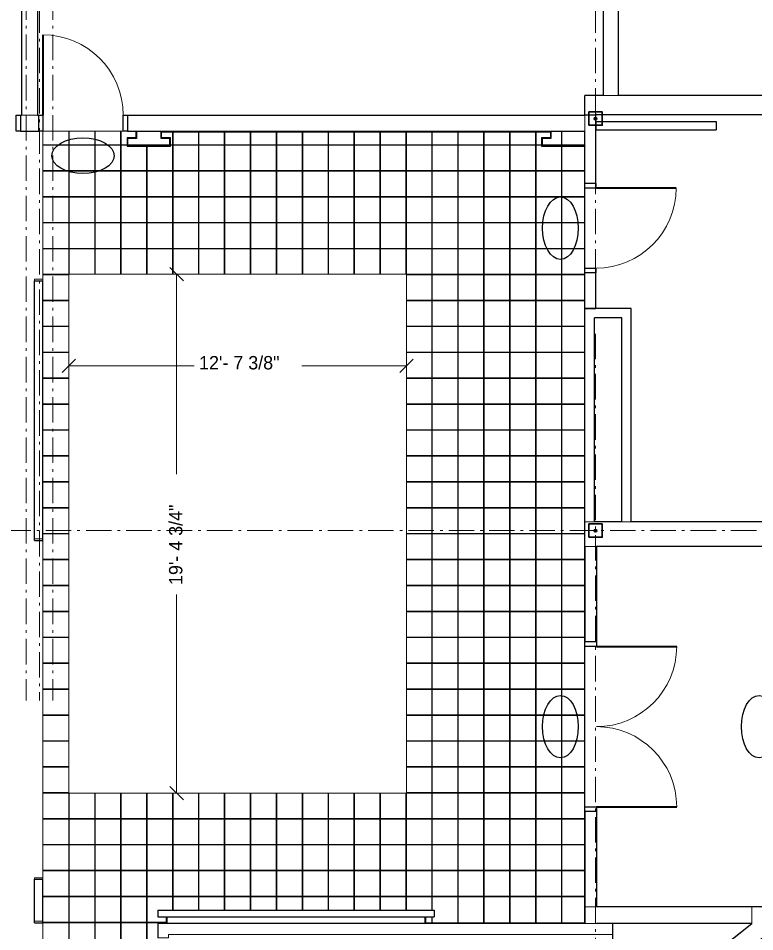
# Model space of a CAD drawing. Extents: x 10076 to 10305, y 10052 to 10157.
# Drawn here: x 10183.75 to 10211.27, y 10095.45 to 10129.6 of the extents above; entities that cross this region are included whole.
import ezdxf

# ---------------------------------------------------------------- set-up
doc = ezdxf.new("R2010")
doc.units = 0
doc.header["$LTSCALE"] = 0.19
doc.header["$PDMODE"] = 32
doc.header["$PDSIZE"] = 0.095
doc.linetypes.add('DOT_DASHED', pattern=[7.7, 5, -1.2, 0.3, -1.2])
for name, color, linetype, lineweight in [('1', 7, 'Continuous', 13), ('10', 7, 'DOT_DASHED', 13), ('12', 7, 'Continuous', 35), ('18', 7, 'Continuous', 13), ('23', 7, 'Continuous', 25), ('25', 7, 'Continuous', 13), ('26', 7, 'Continuous', 25), ('42', 7, 'Continuous', 25)]:
    doc.layers.add(name, color=color, linetype=linetype, lineweight=lineweight)

msp = doc.modelspace()

# ---------------------------------------------------------------- linework, layer by layer
at = {"layer": '1'}
for points in [[(10183.8669, 10125.9796), (10183.8669, 10140.2504), (10184.4711, 10140.2504), (10184.4711, 10125.9796)], [(10205.6117, 10140.2504), (10205.6117, 10126.7087), (10206.1742, 10126.7087), (10206.1742, 10140.2504)], [(10204.9242, 10126.7087), (10204.9242, 10125.99), (10223.8513, 10125.99), (10223.8513, 10126.7087)], [(10183.8356, 10125.9796), (10183.8356, 10125.3754), (10184.5023, 10125.3754), (10184.5023, 10125.9796)], [(10187.8356, 10125.9796), (10187.8356, 10125.3754), (10204.9242, 10125.3754), (10204.9242, 10125.9796)], [(10205.3304, 10123.4171), (10205.3304, 10125.9796), (10204.9242, 10125.9796), (10204.9242, 10123.4171)], [(10205.3304, 10125.99), (10205.3304, 10125.7386), (10205.5705, 10125.7386), (10205.5705, 10125.99)], [(10209.8304, 10125.4275), (10209.8304, 10125.74), (10205.3304, 10125.74), (10205.3304, 10125.4275)], [(10188.1481, 10125.3754), (10188.1481, 10125.1254), (10187.8148, 10125.1254), (10187.8148, 10124.8129), (10189.4398, 10124.8129), (10189.4398, 10125.1254), (10189.1065, 10125.1254), (10189.1065, 10125.3754)], [(10203.6325, 10125.3754), (10203.6325, 10125.1254), (10203.2992, 10125.1254), (10203.2992, 10124.8129), (10204.9242, 10124.8129), (10204.9242, 10125.3754)], [(10184.3565, 10119.8389), (10184.3565, 10110.1306), (10184.669, 10110.1306), (10184.669, 10119.8389)], [(10204.9242, 10120.0837), (10204.9242, 10118.7504), (10205.3304, 10118.7504), (10205.3304, 10120.0837)], [(10204.9242, 10118.7504), (10204.9242, 10110.766), (10206.6534, 10110.766), (10206.6534, 10118.7504)], [(10204.9242, 10109.8493), (10204.9242, 10110.766), (10224.8926, 10110.766), (10224.8926, 10109.8493)], [(10205.3513, 10109.8493), (10205.3513, 10106.2817), (10204.9242, 10106.2817), (10204.9242, 10109.8493)], [(10204.9242, 10099.9484), (10204.9242, 10096.3806), (10205.3513, 10096.3806), (10205.3513, 10099.9484)], [(10184.3565, 10097.4639), (10184.3565, 10095.8389), (10184.669, 10095.8389), (10184.669, 10097.4639)], [(10211.1603, 10095.7556), (10211.1603, 10096.3806), (10204.9242, 10096.3806), (10204.9242, 10095.7556)], [(10211.1603, 10096.3806), (10213.0179, 10096.3806), (10206.1076, 10090.8876), (10205.6117, 10090.8858), (10205.6117, 10091.6266), (10205.9659, 10091.6266), (10211.1603, 10095.7556)], [(10189.3669, 10095.3493), (10189.3669, 10095.2191), (10188.9606, 10095.2191), (10188.9606, 10095.7556), (10205.9659, 10095.7556), (10205.9659, 10095.3493)]]:
    msp.add_lwpolyline(points, close=True, dxfattribs=at)
at = {"layer": '10'}
for p, q in [((10184.544, 10154.0964), (10184.544, 10104.0964)), ((10205.32, 10154.0964), (10205.32, 10118.7504)), ((10184.044, 10151.5744), (10184.044, 10104.0964)), ((10185.044, 10151.5744), (10185.044, 10104.0964)), ((10205.32, 10117.8041), (10205.32, 10071.3549)), ((10227.8946, 10110.4431), (10179.5805, 10110.4431))]:
    msp.add_line(p, q, dxfattribs=at)
at = {"layer": '12'}
for points in [[(10205.07, 10125.5941), (10205.07, 10126.0941), (10205.57, 10126.0941), (10205.57, 10125.5941)], [(10205.07, 10110.1931), (10205.07, 10110.6931), (10205.57, 10110.6931), (10205.57, 10110.1931)]]:
    msp.add_lwpolyline(points, close=True, dxfattribs=at)
for p in [(10205.32, 10125.8441), (10205.32, 10110.4431)]:
    msp.add_point(p, dxfattribs=at)
at = {"layer": '18'}
for p, q in [((10184.669, 10078.5525), (10184.669, 10125.3754)), ((10184.669, 10125.3754), (10187.669, 10125.3754)), ((10185.6377, 10075.4639), (10185.6377, 10125.3754)), ((10185.6586, 10120.0264), (10185.6586, 10125.3754)), ((10186.6065, 10120.0264), (10186.6065, 10125.3754)), ((10186.6273, 10120.0264), (10186.6273, 10125.3754)), ((10187.5752, 10120.0264), (10187.5752, 10125.3754)), ((10187.5961, 10120.0264), (10187.5961, 10125.3754)), ((10203.6325, 10125.3441), (10189.1065, 10125.3441)), ((10189.5127, 10120.0264), (10189.5127, 10125.3754)), ((10189.5336, 10120.0264), (10189.5336, 10125.3754)), ((10190.4815, 10120.0264), (10190.4815, 10125.3754)), ((10190.5023, 10120.0264), (10190.5023, 10125.3754)), ((10191.4502, 10120.0264), (10191.4502, 10125.3754)), ((10191.4711, 10120.0264), (10191.4711, 10125.3754)), ((10192.419, 10120.0264), (10192.419, 10125.3754)), ((10192.4398, 10120.0264), (10192.4398, 10125.3754)), ((10193.3877, 10120.0264), (10193.3877, 10125.3754)), ((10193.4086, 10120.0264), (10193.4086, 10125.3754)), ((10194.3565, 10120.0264), (10194.3565, 10125.3754)), ((10194.3773, 10120.0264), (10194.3773, 10125.3754)), ((10195.3252, 10120.0264), (10195.3252, 10125.3754)), ((10195.3461, 10120.0264), (10195.3461, 10125.3754)), ((10196.294, 10120.0264), (10196.294, 10125.3754)), ((10196.3148, 10120.0264), (10196.3148, 10125.3754)), ((10197.2627, 10120.0264), (10197.2627, 10125.3754)), ((10197.2836, 10120.0264), (10197.2836, 10125.3754)), ((10198.2315, 10120.0264), (10198.2315, 10125.3754)), ((10198.2523, 10096.2556), (10198.2523, 10125.3754)), ((10199.2002, 10096.2523), (10199.2002, 10125.3754)), ((10199.2211, 10096.2523), (10199.2211, 10125.3754)), ((10200.169, 10095.7764), (10200.169, 10125.3754)), ((10200.1898, 10095.7764), (10200.1898, 10125.3754)), ((10201.1377, 10095.7764), (10201.1377, 10125.3754)), ((10201.1586, 10095.7764), (10201.1586, 10125.3754)), ((10202.1065, 10095.7764), (10202.1065, 10125.3754)), ((10202.1273, 10095.7764), (10202.1273, 10125.3754)), ((10203.0752, 10095.7764), (10203.0752, 10125.3754)), ((10203.0961, 10095.7764), (10203.0961, 10125.3754)), ((10204.044, 10095.7764), (10204.044, 10125.3754)), ((10204.0648, 10095.7764), (10204.0648, 10125.3754)), ((10184.669, 10124.8702), (10204.9034, 10124.8702)), ((10184.669, 10124.8493), (10204.9034, 10124.8493)), ((10188.544, 10120.0264), (10188.544, 10124.8129)), ((10188.5648, 10120.0264), (10188.5648, 10124.8129)), ((10204.9034, 10095.7556), (10204.9034, 10124.8129)), ((10184.669, 10123.9014), (10204.9034, 10123.9014)), ((10184.669, 10123.8806), (10204.9034, 10123.8806)), ((10204.9242, 10123.2504), (10204.9242, 10120.2504)), ((10184.669, 10122.9327), (10204.9034, 10122.9327)), ((10184.669, 10122.9118), (10204.9034, 10122.9118)), ((10184.669, 10121.9639), (10204.9034, 10121.9639)), ((10184.669, 10121.9431), (10204.9034, 10121.9431)), ((10184.669, 10120.9952), (10204.9034, 10120.9952)), ((10184.669, 10120.9743), (10204.9034, 10120.9743)), ((10189.419, 10120.2764), (10189.919, 10119.7764)), ((10184.669, 10120.0264), (10204.9034, 10120.0264)), ((10184.669, 10120.0056), (10185.6377, 10120.0056)), ((10189.669, 10120.0264), (10189.669, 10112.5488)), ((10198.2523, 10120.0056), (10204.9034, 10120.0056)), ((10184.669, 10119.0577), (10185.6377, 10119.0577)), ((10184.669, 10119.0368), (10185.6377, 10119.0368)), ((10198.2523, 10119.0577), (10204.9034, 10119.0577)), ((10198.2523, 10119.0368), (10204.9034, 10119.0368)), ((10184.669, 10118.0889), (10185.6377, 10118.0889)), ((10184.669, 10118.0681), (10185.6377, 10118.0681)), ((10198.2523, 10118.0889), (10204.9034, 10118.0889)), ((10198.2523, 10118.0681), (10204.9034, 10118.0681)), ((10184.669, 10117.1202), (10185.6377, 10117.1202)), ((10184.669, 10117.0993), (10185.6377, 10117.0993)), ((10198.2523, 10117.1202), (10204.9034, 10117.1202)), ((10198.2523, 10117.0993), (10204.9034, 10117.0993)), ((10185.3877, 10116.3493), (10185.8877, 10116.8493)), ((10198.0023, 10116.3493), (10198.5023, 10116.8493)), ((10185.6377, 10116.5993), (10190.3206, 10116.5993)), ((10194.3486, 10116.5993), (10198.2523, 10116.5993)), ((10184.669, 10116.1514), (10185.6377, 10116.1514)), ((10184.669, 10116.1306), (10185.6377, 10116.1306)), ((10198.2523, 10116.1514), (10204.9034, 10116.1514)), ((10198.2523, 10116.1306), (10204.9034, 10116.1306)), ((10184.669, 10115.1827), (10185.6377, 10115.1827)), ((10184.669, 10115.1618), (10185.6377, 10115.1618)), ((10198.2523, 10115.1827), (10204.9034, 10115.1827)), ((10198.2523, 10115.1618), (10204.9034, 10115.1618)), ((10184.669, 10114.2139), (10185.6377, 10114.2139)), ((10184.669, 10114.1931), (10185.6377, 10114.1931)), ((10198.2523, 10114.2139), (10204.9034, 10114.2139)), ((10198.2523, 10114.1931), (10204.9034, 10114.1931)), ((10184.669, 10113.2452), (10185.6377, 10113.2452)), ((10184.669, 10113.2243), (10185.6377, 10113.2243)), ((10198.2523, 10113.2452), (10204.9034, 10113.2452)), ((10198.2523, 10113.2243), (10204.9034, 10113.2243)), ((10184.669, 10112.2764), (10185.6377, 10112.2764)), ((10184.669, 10112.2556), (10185.6377, 10112.2556)), ((10198.2523, 10112.2764), (10204.9034, 10112.2764)), ((10198.2523, 10112.2556), (10204.9034, 10112.2556)), ((10184.669, 10111.3077), (10185.6377, 10111.3077)), ((10184.669, 10111.2868), (10185.6377, 10111.2868)), ((10198.2523, 10111.3077), (10204.9034, 10111.3077)), ((10198.2523, 10111.2868), (10204.9034, 10111.2868)), ((10184.669, 10110.3389), (10185.6377, 10110.3389)), ((10184.669, 10110.3181), (10185.6377, 10110.3181)), ((10198.2523, 10110.3389), (10204.9034, 10110.3389)), ((10198.2523, 10110.3181), (10204.9034, 10110.3181)), ((10184.669, 10109.3702), (10185.6377, 10109.3702)), ((10184.669, 10109.3493), (10185.6377, 10109.3493)), ((10198.2523, 10109.3702), (10204.9034, 10109.3702)), ((10198.2523, 10109.3493), (10204.9034, 10109.3493)), ((10184.669, 10108.4014), (10185.6377, 10108.4014)), ((10184.669, 10108.3806), (10185.6377, 10108.3806)), ((10198.2523, 10108.4014), (10204.9034, 10108.4014)), ((10198.2523, 10108.3806), (10204.9034, 10108.3806)), ((10189.669, 10108.0527), (10189.669, 10100.6306)), ((10184.669, 10107.4327), (10185.6377, 10107.4327)), ((10184.669, 10107.4118), (10185.6377, 10107.4118)), ((10198.2523, 10107.4327), (10204.9034, 10107.4327)), ((10198.2523, 10107.4118), (10204.9034, 10107.4118)), ((10184.669, 10106.4639), (10185.6377, 10106.4639)), ((10184.669, 10106.4431), (10185.6377, 10106.4431)), ((10198.2523, 10106.4639), (10204.9034, 10106.4639)), ((10198.2523, 10106.4431), (10204.9034, 10106.4431)), ((10204.9242, 10100.1151), (10204.9242, 10106.1151)), ((10184.669, 10105.4952), (10185.6377, 10105.4952)), ((10184.669, 10105.4743), (10185.6377, 10105.4743)), ((10198.2523, 10105.4952), (10204.9034, 10105.4952)), ((10198.2523, 10105.4743), (10204.9034, 10105.4743)), ((10184.669, 10104.5264), (10185.6377, 10104.5264)), ((10184.669, 10104.5056), (10185.6377, 10104.5056)), ((10198.2523, 10104.5264), (10204.9034, 10104.5264)), ((10198.2523, 10104.5056), (10204.9034, 10104.5056)), ((10184.669, 10103.5577), (10185.6377, 10103.5577)), ((10184.669, 10103.5368), (10185.6377, 10103.5368)), ((10198.2523, 10103.5577), (10204.9034, 10103.5577)), ((10198.2523, 10103.5368), (10204.9034, 10103.5368)), ((10184.669, 10102.5889), (10185.6377, 10102.5889)), ((10184.669, 10102.5681), (10185.6377, 10102.5681)), ((10198.2523, 10102.5889), (10204.9034, 10102.5889)), ((10198.2523, 10102.5681), (10204.9034, 10102.5681)), ((10184.669, 10101.6202), (10185.6377, 10101.6202)), ((10184.669, 10101.5993), (10185.6377, 10101.5993)), ((10198.2523, 10101.6202), (10204.9034, 10101.6202)), ((10198.2523, 10101.5993), (10204.9034, 10101.5993)), ((10184.669, 10100.6514), (10185.6377, 10100.6514)), ((10189.419, 10100.8806), (10189.919, 10100.3806)), ((10198.2523, 10100.6514), (10204.9034, 10100.6514)), ((10184.669, 10100.6306), (10204.9034, 10100.6306)), ((10185.6586, 10075.4639), (10185.6586, 10100.6304)), ((10186.6065, 10075.4639), (10186.6065, 10100.6306)), ((10186.6273, 10075.4639), (10186.6273, 10100.6306)), ((10187.5752, 10075.4639), (10187.5752, 10100.6306)), ((10187.5961, 10075.4639), (10187.5961, 10100.6306)), ((10188.544, 10075.4639), (10188.544, 10100.6306)), ((10188.5648, 10075.4639), (10188.5648, 10100.6306)), ((10189.5127, 10096.2556), (10189.5127, 10100.6306)), ((10189.5336, 10096.2556), (10189.5336, 10100.6306)), ((10190.4815, 10096.2556), (10190.4815, 10100.6306)), ((10190.5023, 10096.2556), (10190.5023, 10100.6306)), ((10191.4502, 10096.2556), (10191.4502, 10100.6306)), ((10191.4711, 10096.2556), (10191.4711, 10100.6306)), ((10192.419, 10096.2556), (10192.419, 10100.6306)), ((10192.4398, 10096.2556), (10192.4398, 10100.6306)), ((10193.3877, 10096.2556), (10193.3877, 10100.6306)), ((10193.4086, 10096.2556), (10193.4086, 10100.6306)), ((10194.3565, 10096.2556), (10194.3565, 10100.6306)), ((10194.3773, 10096.2556), (10194.3773, 10100.6306)), ((10195.3252, 10096.2556), (10195.3252, 10100.6306)), ((10195.3461, 10096.2556), (10195.3461, 10100.6306)), ((10196.294, 10096.2556), (10196.294, 10100.6306)), ((10196.3148, 10096.2556), (10196.3148, 10100.6306)), ((10197.2627, 10096.2556), (10197.2627, 10100.6306)), ((10197.2836, 10096.2556), (10197.2836, 10100.6306)), ((10198.2315, 10096.2556), (10198.2315, 10100.6306)), ((10184.669, 10099.6827), (10204.9034, 10099.6827)), ((10184.669, 10099.6618), (10204.9034, 10099.6618)), ((10184.669, 10098.7139), (10204.9034, 10098.7139)), ((10184.669, 10098.6931), (10204.9034, 10098.6931)), ((10184.669, 10097.7452), (10204.9034, 10097.7452)), ((10184.669, 10097.7243), (10204.9034, 10097.7243)), ((10184.669, 10096.7764), (10204.9034, 10096.7764)), ((10184.669, 10096.7556), (10204.9034, 10096.7556)), ((10199.2002, 10095.7764), (10199.2002, 10096.0056)), ((10199.2211, 10095.7764), (10199.2211, 10096.0056)), ((10184.669, 10095.8077), (10189.294, 10095.8077)), ((10184.669, 10095.7868), (10189.294, 10095.7868)), ((10204.9242, 10095.7764), (10198.9606, 10095.7764))]:
    msp.add_line(p, q, dxfattribs=at)
at = {"layer": '23'}
for p, q in [((10183.8669, 10140.2504), (10183.8669, 10125.9796)), ((10184.4711, 10140.2504), (10184.4711, 10125.9796)), ((10205.6117, 10126.7087), (10205.6117, 10140.2504)), ((10206.1742, 10126.7087), (10206.1742, 10140.2504)), ((10205.6117, 10126.7087), (10204.9242, 10126.7087)), ((10204.9242, 10125.9796), (10204.9242, 10126.7087)), ((10223.8513, 10126.7087), (10206.1742, 10126.7087)), ((10183.8356, 10125.9796), (10183.8669, 10125.9796)), ((10183.8356, 10125.9796), (10183.8356, 10125.3754)), ((10184.4711, 10125.9796), (10184.5023, 10125.9796)), ((10184.5023, 10125.9796), (10184.5023, 10125.3754)), ((10187.8356, 10125.9796), (10204.9242, 10125.9796)), ((10187.8356, 10125.9796), (10187.8356, 10125.3754)), ((10205.3304, 10123.4171), (10205.3304, 10126.0408)), ((10222.5596, 10125.99), (10205.3304, 10125.99)), ((10205.3304, 10125.74), (10209.8304, 10125.74)), ((10205.3304, 10125.74), (10205.3304, 10125.4275)), ((10209.8304, 10125.74), (10209.8304, 10125.4275)), ((10183.8356, 10125.3754), (10184.5023, 10125.3754)), ((10187.8356, 10125.3754), (10188.1481, 10125.3754)), ((10188.1481, 10125.3754), (10188.1481, 10125.1254)), ((10188.169, 10125.3754), (10188.169, 10125.1046)), ((10188.169, 10125.3754), (10189.0856, 10125.3754)), ((10189.0856, 10125.1046), (10189.0856, 10125.3754)), ((10189.1065, 10125.1254), (10189.1065, 10125.3754)), ((10189.1065, 10125.3754), (10203.6325, 10125.3754)), ((10203.6325, 10125.3754), (10203.6325, 10125.1254)), ((10203.6534, 10125.3754), (10203.6534, 10125.1046)), ((10203.6534, 10125.3754), (10204.9242, 10125.3754)), ((10204.9242, 10123.4171), (10204.9242, 10125.3754)), ((10205.3304, 10125.4275), (10209.8304, 10125.4275)), ((10188.1481, 10125.1254), (10187.8148, 10125.1254)), ((10187.8148, 10125.1254), (10187.8148, 10124.8129)), ((10188.169, 10125.1046), (10187.8356, 10125.1046)), ((10187.8356, 10125.1046), (10187.8356, 10124.8337)), ((10189.419, 10125.1046), (10189.0856, 10125.1046)), ((10189.4398, 10125.1254), (10189.1065, 10125.1254)), ((10189.419, 10124.8337), (10189.419, 10125.1046)), ((10189.4398, 10124.8129), (10189.4398, 10125.1254)), ((10203.6325, 10125.1254), (10203.2992, 10125.1254)), ((10203.2992, 10125.1254), (10203.2992, 10124.8129)), ((10203.6534, 10125.1046), (10203.32, 10125.1046)), ((10203.32, 10125.1046), (10203.32, 10124.8337)), ((10187.8148, 10124.8129), (10189.4398, 10124.8129)), ((10187.8356, 10124.8337), (10189.419, 10124.8337)), ((10203.2992, 10124.8129), (10204.9242, 10124.8129)), ((10205.3304, 10123.4171), (10204.9242, 10123.4171)), ((10184.3565, 10110.0785), (10184.3565, 10119.7868)), ((10184.3565, 10119.7868), (10184.669, 10119.7868)), ((10184.669, 10110.0785), (10184.669, 10119.7868)), ((10204.9242, 10118.7504), (10204.9242, 10120.0837)), ((10205.3304, 10120.0837), (10204.9242, 10120.0837)), ((10205.3304, 10118.7504), (10205.3304, 10120.0837)), ((10204.9242, 10109.8493), (10204.9242, 10118.7504)), ((10206.6534, 10118.7504), (10204.9242, 10118.7504)), ((10204.9242, 10118.7504), (10205.3304, 10118.7504)), ((10206.6534, 10110.766), (10206.6534, 10118.7504)), ((10205.2784, 10110.766), (10205.2784, 10118.3962)), ((10206.2992, 10118.3962), (10205.2784, 10118.3962)), ((10206.2992, 10110.766), (10206.2992, 10118.3962)), ((10206.2992, 10110.766), (10205.2784, 10110.766)), ((10224.8926, 10110.766), (10206.6534, 10110.766)), ((10184.3565, 10110.0785), (10184.669, 10110.0785)), ((10204.9242, 10109.8493), (10204.9242, 10106.2817)), ((10212.3513, 10109.8493), (10205.3513, 10109.8493)), ((10205.3513, 10109.8493), (10205.3513, 10106.2817)), ((10205.3513, 10106.2817), (10204.9242, 10106.2817)), ((10204.9242, 10099.9484), (10204.9242, 10095.7556)), ((10205.3513, 10099.9484), (10204.9242, 10099.9484)), ((10205.3513, 10099.9484), (10205.3513, 10096.3806)), ((10184.3565, 10095.7868), (10184.3565, 10097.4118)), ((10184.3565, 10097.4118), (10184.669, 10097.4118)), ((10184.669, 10095.7868), (10184.669, 10097.4118)), ((10188.9606, 10096.2556), (10188.9606, 10096.0056)), ((10213.0179, 10096.3806), (10205.3513, 10096.3806)), ((10188.9606, 10096.0056), (10189.294, 10096.0056)), ((10189.294, 10095.7556), (10189.294, 10096.0056)), ((10189.3148, 10095.7556), (10189.3148, 10096.0056)), ((10189.3148, 10096.0056), (10198.9398, 10096.0056)), ((10198.9398, 10096.0056), (10198.9398, 10095.7556)), ((10198.9606, 10096.0056), (10199.294, 10096.0056)), ((10198.9606, 10096.0056), (10198.9606, 10095.7556)), ((10184.3565, 10095.7868), (10184.669, 10095.7868)), ((10188.9606, 10095.7556), (10188.9606, 10095.2191)), ((10189.294, 10095.7556), (10188.9606, 10095.7556)), ((10198.9398, 10095.7556), (10189.3148, 10095.7556)), ((10204.9242, 10095.7556), (10198.9606, 10095.7556)), ((10211.1603, 10095.7556), (10205.3513, 10095.7556)), ((10205.9659, 10095.7556), (10205.3513, 10095.7556)), ((10205.9659, 10091.6266), (10211.1603, 10095.7556)), ((10205.9659, 10091.6266), (10205.9659, 10095.7556))]:
    msp.add_line(p, q, dxfattribs=at)
for points in [[(10203.32, 10124.8337), (10204.9242, 10124.8337), (10204.9242, 10124.8129)], [(10188.9606, 10096.2556), (10199.294, 10096.2556), (10199.294, 10096.0056)]]:
    msp.add_lwpolyline(points, dxfattribs=at)
at = {"layer": '25', "lineweight": 40}
for p, q in [((10184.669, 10128.9796), (10184.669, 10125.9796)), ((10208.3304, 10123.2504), (10205.3304, 10123.2504)), ((10205.3513, 10106.1151), (10208.3513, 10106.1151)), ((10205.3513, 10100.1149), (10208.3514, 10100.1149))]:
    msp.add_line(p, q, dxfattribs=at)
at = {"layer": '25'}
for centre, radius, start, end in [((10184.669, 10125.9796), 3, 0.00001, 90), ((10205.3304, 10123.2504), 3, 270.00001, 0.00001), ((10205.3513, 10106.1151), 3.0001, 270.00005, 359.99974), ((10205.3513, 10100.1149), 3.0001, 0.00025, 89.99995)]:
    msp.add_arc(centre, radius, start, end, dxfattribs=at)
at = {"layer": '26'}
for points in [[(10183.8356, 10125.3754), (10183.669, 10125.3754), (10183.669, 10125.9796), (10183.8356, 10125.9796)], [(10184.5023, 10125.9796), (10184.669, 10125.9796), (10184.669, 10125.3754), (10184.5023, 10125.3754)], [(10187.8356, 10125.3754), (10187.669, 10125.3754), (10187.669, 10125.9796), (10187.8356, 10125.9796)], [(10205.3304, 10123.4171), (10205.3304, 10123.2504), (10204.9242, 10123.2504), (10204.9242, 10123.4171)], [(10204.9242, 10120.0837), (10204.9242, 10120.2504), (10205.3304, 10120.2504), (10205.3304, 10120.0837)], [(10205.3513, 10106.2817), (10205.3513, 10106.1151), (10204.9242, 10106.1151), (10204.9242, 10106.2817)], [(10204.9242, 10099.9484), (10204.9242, 10100.1151), (10205.3513, 10100.1151), (10205.3513, 10099.9484)]]:
    msp.add_lwpolyline(points, dxfattribs=at)
at = {"layer": '42'}
for centre, major_axis in [((10186.169, 10124.4587), (1.1667, 0)), ((10204.0075, 10121.7504), (0, -1.1667)), ((10204.0075, 10103.1151), (0, -1.1667)), ((10211.4346, 10103.1151), (0, -1.1667))]:
    msp.add_ellipse(centre, major_axis=major_axis, ratio=0.571429, dxfattribs=at)

# ---------------------------------------------------------------- texts
at = {"layer": '18'}
msp.add_text('12\'- 7 3/8"', height=0.5, dxfattribs=at).set_placement((10190.5068, 10116.4698))
msp.add_text('19\'- 4 3/4"', height=0.5, rotation=90, dxfattribs=at).set_placement((10189.8833, 10108.4112))

doc.saveas('drawing.dxf')
